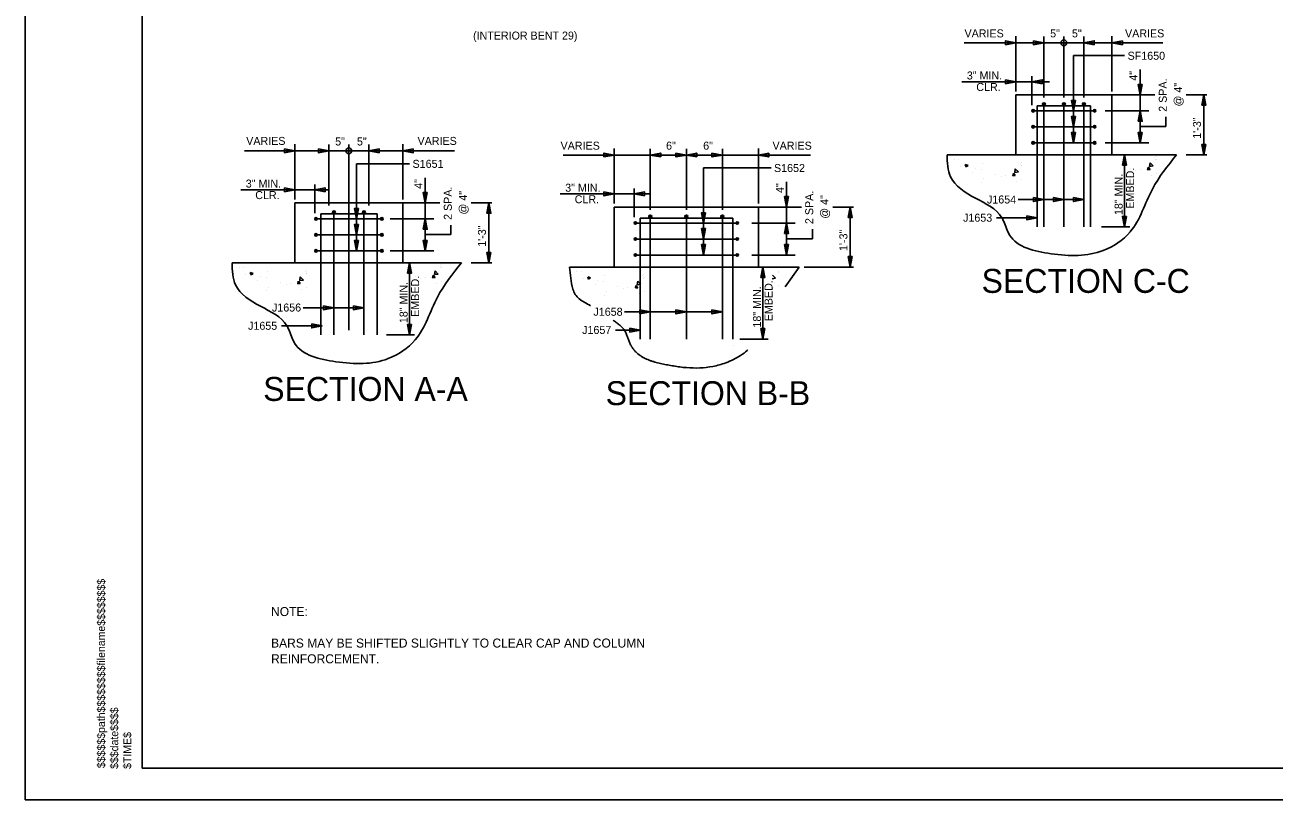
# Model space of a CAD drawing. Extents: x -144.4 to -96.3, y -117.1 to -87.8.
# Drawn here: x -144.35 to -118.31, y -117.06 to -100.91 of the extents above; entities that cross this region are included whole.
import ezdxf

# ---------------------------------------------------------------- set-up
doc = ezdxf.new("R2010")
doc.units = 0
for name, color, linetype in [('BR_AUTO DIMENSION', 7, 'Continuous'), ('BR_BORDER LINES', 7, 'Continuous'), ('BR_CENTER LINES', 7, 'Continuous'), ('BR_CONCRETE', 7, 'Continuous'), ('BR_REBAR', 7, 'Continuous'), ('BR_TEXT', 7, 'Continuous'), ('Level 31', 7, 'Continuous'), ('RD_SHT_ID', 7, 'Continuous')]:
    doc.layers.add(name, color=color, linetype=linetype)

msp = doc.modelspace()

# ---------------------------------------------------------------- linework, layer by layer
at = {"layer": 'BR_AUTO DIMENSION'}
for p, q in [((-123.71, -102.298), (-123.71, -101.149)), ((-123.127, -102.424), (-123.127, -101.154)), ((-122.71, -102.424), (-122.71, -101.154)), ((-122.294, -102.424), (-122.294, -101.154)), ((-121.71, -102.298), (-121.71, -101.149)), ((-124.788, -101.285), (-120.65, -101.285)), ((-121.446, -101.553), (-122.51, -101.553)), ((-122.51, -101.553), (-122.51, -103.369)), ((-123.377, -102.583), (-123.377, -101.984)), ((-121.121, -103.369), (-121.121, -101.845)), ((-124.835, -102.096), (-123.013, -102.096)), ((-121.794, -102.369), (-120.814, -102.369)), ((-120.161, -102.369), (-119.73, -102.369)), ((-119.795, -102.369), (-119.795, -103.619)), ((-121.849, -102.702), (-120.942, -102.702)), ((-120.585, -103.03), (-120.585, -102.831)), ((-121.121, -103.03), (-120.585, -103.03)), ((-139.781, -103.536), (-135.407, -103.536)), ((-138.729, -104.55), (-138.729, -103.401)), ((-138.02, -104.675), (-138.02, -103.406)), ((-137.604, -104.675), (-137.604, -103.406)), ((-137.187, -104.675), (-137.187, -103.406)), ((-136.479, -104.55), (-136.479, -103.401)), ((-133.144, -103.624), (-127.986, -103.624)), ((-132.075, -104.637), (-132.075, -103.488)), ((-131.325, -104.763), (-131.325, -103.494)), ((-130.575, -104.763), (-130.575, -103.494)), ((-129.825, -104.763), (-129.825, -103.494)), ((-129.075, -104.637), (-129.075, -103.488)), ((-121.849, -103.369), (-120.942, -103.369)), ((-121.448, -103.619), (-121.448, -105.119)), ((-120.161, -103.619), (-119.73, -103.619)), ((-136.34, -103.805), (-137.444, -103.805)), ((-137.444, -103.805), (-137.444, -105.62)), ((-136.014, -105.62), (-136.014, -104.097)), ((-128.811, -103.892), (-130.217, -103.892)), ((-130.217, -103.892), (-130.217, -105.708)), ((-139.854, -104.348), (-138.032, -104.348)), ((-138.316, -104.834), (-138.316, -104.235)), ((-131.661, -104.922), (-131.661, -104.323)), ((-128.486, -105.708), (-128.486, -104.185)), ((-136.479, -104.62), (-135.707, -104.62)), ((-135.054, -104.62), (-134.623, -104.62)), ((-134.689, -104.62), (-134.689, -105.87)), ((-133.2, -104.435), (-131.346, -104.435)), ((-122.294, -104.553), (-123.663, -104.553)), ((-129.159, -104.708), (-128.179, -104.708)), ((-127.526, -104.708), (-127.095, -104.708)), ((-127.16, -104.708), (-127.16, -105.958)), ((-136.742, -104.954), (-135.835, -104.954)), ((-135.478, -105.281), (-135.478, -105.083)), ((-129.214, -105.041), (-128.307, -105.041)), ((-127.95, -105.369), (-127.95, -105.171)), ((-123.268, -104.932), (-124.112, -104.932)), ((-121.927, -105.119), (-121.34, -105.119)), ((-136.014, -105.281), (-135.478, -105.281)), ((-128.486, -105.369), (-127.95, -105.369)), ((-136.742, -105.62), (-135.835, -105.62)), ((-129.214, -105.708), (-128.307, -105.708)), ((-136.342, -105.87), (-136.342, -107.37)), ((-135.054, -105.87), (-134.623, -105.87)), ((-128.979, -105.958), (-128.979, -107.458)), ((-128.122, -105.958), (-127.095, -105.958)), ((-137.291, -106.805), (-138.556, -106.805)), ((-129.825, -106.892), (-131.865, -106.892)), ((-138.161, -107.184), (-139.006, -107.184)), ((-131.535, -107.271), (-132.047, -107.271)), ((-136.82, -107.37), (-136.234, -107.37)), ((-129.458, -107.458), (-128.871, -107.458))]:
    msp.add_line(p, q, dxfattribs=at)
for points in [[(-123.926, -101.326), (-123.71, -101.285), (-123.926, -101.243)], [(-123.344, -101.243), (-123.127, -101.285), (-123.344, -101.326)], [(-122.077, -101.326), (-122.294, -101.285), (-122.077, -101.243)], [(-121.493, -101.243), (-121.71, -101.285), (-121.493, -101.326)], [(-123.926, -102.054), (-123.71, -102.096), (-123.926, -102.138)], [(-123.16, -102.138), (-123.377, -102.096), (-123.16, -102.054)], [(-121.079, -102.152), (-121.121, -102.369), (-121.163, -102.152)], [(-122.469, -102.485), (-122.51, -102.702), (-122.552, -102.485)], [(-119.837, -102.585), (-119.795, -102.369), (-119.754, -102.585)], [(-122.469, -102.819), (-122.51, -103.035), (-122.552, -102.819)], [(-121.163, -102.919), (-121.121, -102.702), (-121.079, -102.919)], [(-122.469, -103.152), (-122.51, -103.369), (-122.552, -103.152)], [(-121.079, -103.152), (-121.121, -103.369), (-121.163, -103.152)], [(-138.945, -103.578), (-138.729, -103.536), (-138.945, -103.495)], [(-138.237, -103.495), (-138.02, -103.536), (-138.237, -103.578)], [(-136.97, -103.578), (-137.187, -103.536), (-136.97, -103.495)], [(-136.262, -103.495), (-136.479, -103.536), (-136.262, -103.578)], [(-132.291, -103.665), (-132.075, -103.624), (-132.291, -103.582)], [(-131.108, -103.665), (-131.325, -103.624), (-131.108, -103.582)], [(-130.791, -103.582), (-130.575, -103.624), (-130.791, -103.665)], [(-130.358, -103.665), (-130.575, -103.624), (-130.358, -103.582)], [(-130.041, -103.582), (-129.825, -103.624), (-130.041, -103.665)], [(-128.858, -103.582), (-129.075, -103.624), (-128.858, -103.665)], [(-121.49, -103.835), (-121.448, -103.619), (-121.407, -103.835)], [(-119.754, -103.402), (-119.795, -103.619), (-119.837, -103.402)], [(-138.945, -104.306), (-138.729, -104.348), (-138.945, -104.389)], [(-138.099, -104.389), (-138.316, -104.348), (-138.099, -104.306)], [(-135.973, -104.404), (-136.014, -104.62), (-136.056, -104.404)], [(-132.291, -104.394), (-132.075, -104.435), (-132.291, -104.477)], [(-131.445, -104.477), (-131.661, -104.435), (-131.445, -104.394)], [(-134.73, -104.837), (-134.689, -104.62), (-134.647, -104.837)], [(-128.444, -104.491), (-128.486, -104.708), (-128.527, -104.491)], [(-123.344, -104.511), (-123.127, -104.553), (-123.344, -104.595)], [(-122.927, -104.511), (-122.71, -104.553), (-122.927, -104.595)], [(-122.51, -104.511), (-122.294, -104.553), (-122.51, -104.595)], [(-137.403, -104.737), (-137.444, -104.954), (-137.486, -104.737)], [(-130.176, -104.825), (-130.217, -105.041), (-130.259, -104.825)], [(-127.202, -104.925), (-127.16, -104.708), (-127.119, -104.925)], [(-123.484, -104.891), (-123.268, -104.932), (-123.484, -104.974)], [(-121.407, -104.902), (-121.448, -105.119), (-121.49, -104.902)], [(-137.403, -105.07), (-137.444, -105.287), (-137.486, -105.07)], [(-136.056, -105.17), (-136.014, -104.954), (-135.973, -105.17)], [(-130.176, -105.158), (-130.217, -105.375), (-130.259, -105.158)], [(-128.527, -105.258), (-128.486, -105.041), (-128.444, -105.258)], [(-137.403, -105.404), (-137.444, -105.62), (-137.486, -105.404)], [(-135.973, -105.404), (-136.014, -105.62), (-136.056, -105.404)], [(-134.647, -105.654), (-134.689, -105.87), (-134.73, -105.654)], [(-130.176, -105.491), (-130.217, -105.708), (-130.259, -105.491)], [(-128.444, -105.491), (-128.486, -105.708), (-128.527, -105.491)], [(-136.383, -106.087), (-136.342, -105.87), (-136.3, -106.087)], [(-129.021, -106.175), (-128.979, -105.958), (-128.938, -106.175)], [(-127.119, -105.741), (-127.16, -105.958), (-127.202, -105.741)], [(-138.133, -106.763), (-137.916, -106.805), (-138.133, -106.846)], [(-137.508, -106.763), (-137.291, -106.805), (-137.508, -106.846)], [(-131.541, -106.851), (-131.325, -106.892), (-131.541, -106.934)], [(-130.791, -106.851), (-130.575, -106.892), (-130.791, -106.934)], [(-130.041, -106.851), (-129.825, -106.892), (-130.041, -106.934)], [(-138.378, -107.142), (-138.161, -107.184), (-138.378, -107.226)], [(-136.3, -107.154), (-136.342, -107.37), (-136.383, -107.154)], [(-131.752, -107.23), (-131.535, -107.271), (-131.752, -107.313)], [(-128.938, -107.241), (-128.979, -107.458), (-129.021, -107.241)]]:
    msp.add_lwpolyline(points, close=True, dxfattribs=at)
for centre in [(-122.71, -101.285), (-137.604, -103.536)]:
    msp.add_circle(centre, 0.06, dxfattribs=at)
at = {"layer": 'BR_BORDER LINES'}
for q in [(-141.912, -88.468), (-97.136, -116.398)]:
    msp.add_line((-141.912, -116.398), q, dxfattribs=at)
at = {"layer": 'BR_CENTER LINES'}
msp.add_line((-137.604, -104.353), (-137.604, -107.275), dxfattribs=at)
at = {"layer": 'BR_CONCRETE'}
for p, q in [((-123.71, -102.369), (-121.71, -102.369)), ((-123.71, -102.369), (-123.71, -103.619)), ((-121.71, -102.369), (-121.71, -103.619)), ((-125.143, -103.619), (-120.363, -103.619)), ((-124.99, -103.715), (-124.99, -103.715)), ((-124.899, -103.713), (-124.899, -103.713)), ((-124.858, -103.867), (-124.858, -103.867)), ((-124.766, -103.879), (-124.766, -103.879)), ((-124.707, -103.844), (-124.765, -103.821)), ((-124.748, -103.872), (-124.765, -103.822)), ((-124.707, -103.844), (-124.748, -103.872)), ((-124.413, -103.797), (-124.413, -103.797)), ((-123.62, -103.795), (-123.62, -103.795)), ((-123.6, -103.848), (-123.6, -103.848)), ((-123.598, -103.776), (-123.598, -103.776)), ((-123.592, -103.843), (-123.592, -103.843)), ((-120.966, -103.93), (-120.956, -103.877)), ((-120.916, -103.925), (-120.956, -103.877)), ((-120.925, -103.864), (-120.916, -103.785)), ((-120.851, -103.852), (-120.925, -103.864)), ((-120.851, -103.852), (-120.916, -103.785)), ((-120.813, -103.67), (-120.813, -103.67)), ((-120.793, -103.723), (-120.793, -103.723)), ((-120.791, -103.651), (-120.791, -103.651)), ((-120.785, -103.718), (-120.785, -103.718)), ((-124.613, -103.979), (-124.613, -103.979)), ((-124.558, -103.906), (-124.558, -103.906)), ((-124.43, -103.925), (-124.43, -103.925)), ((-124.383, -104.122), (-124.383, -104.122)), ((-124.136, -104.027), (-124.136, -104.027)), ((-124.018, -104.066), (-124.018, -104.066)), ((-123.927, -104.055), (-123.927, -104.055)), ((-123.773, -104.055), (-123.763, -104.002)), ((-123.723, -104.05), (-123.773, -104.054)), ((-123.723, -104.05), (-123.763, -104.002)), ((-123.732, -103.989), (-123.723, -103.91)), ((-123.658, -103.977), (-123.732, -103.989)), ((-123.658, -103.977), (-123.723, -103.91)), ((-123.59, -104.125), (-123.59, -104.125)), ((-121.333, -104.067), (-121.333, -104.067)), ((-121.328, -103.902), (-121.328, -103.902)), ((-121.242, -104.065), (-121.242, -104.065)), ((-121.211, -103.941), (-121.211, -103.941)), ((-121.12, -103.93), (-121.12, -103.93)), ((-120.916, -103.925), (-120.966, -103.929)), ((-120.888, -104.048), (-120.888, -104.048)), ((-120.783, -104), (-120.783, -104)), ((-124.42, -104.203), (-124.42, -104.203)), ((-123.695, -104.173), (-123.695, -104.173)), ((-138.729, -104.62), (-136.479, -104.62)), ((-138.729, -104.62), (-138.729, -105.87)), ((-136.479, -104.62), (-136.479, -105.87)), ((-132.075, -104.708), (-129.075, -104.708)), ((-132.075, -104.708), (-132.075, -105.958)), ((-129.075, -104.708), (-129.075, -105.958)), ((-140.036, -105.87), (-135.257, -105.87)), ((-139.883, -105.967), (-139.883, -105.967)), ((-139.792, -105.965), (-139.792, -105.965)), ((-135.706, -105.922), (-135.706, -105.922)), ((-135.684, -105.903), (-135.684, -105.903)), ((-135.678, -105.97), (-135.678, -105.97)), ((-133.007, -105.958), (-128.228, -105.958)), ((-128.519, -106.372), (-128.228, -105.958)), ((-139.751, -106.118), (-139.751, -106.118)), ((-139.66, -106.131), (-139.66, -106.131)), ((-139.6, -106.095), (-139.658, -106.073)), ((-139.642, -106.123), (-139.658, -106.073)), ((-139.6, -106.095), (-139.641, -106.123)), ((-139.506, -106.231), (-139.506, -106.231)), ((-139.451, -106.158), (-139.451, -106.158)), ((-139.323, -106.177), (-139.323, -106.177)), ((-139.306, -106.048), (-139.306, -106.048)), ((-138.626, -106.241), (-138.616, -106.162)), ((-138.551, -106.229), (-138.626, -106.241)), ((-138.551, -106.229), (-138.616, -106.161)), ((-138.513, -106.047), (-138.513, -106.047)), ((-138.494, -106.099), (-138.494, -106.099)), ((-138.491, -106.028), (-138.491, -106.028)), ((-138.485, -106.095), (-138.485, -106.095)), ((-136.222, -106.154), (-136.222, -106.154)), ((-136.104, -106.193), (-136.104, -106.193)), ((-136.013, -106.181), (-136.013, -106.181)), ((-135.859, -106.181), (-135.849, -106.129)), ((-135.809, -106.177), (-135.859, -106.181)), ((-135.809, -106.177), (-135.849, -106.129)), ((-135.818, -106.116), (-135.809, -106.037)), ((-135.744, -106.104), (-135.818, -106.116)), ((-135.744, -106.104), (-135.809, -106.036)), ((-135.687, -105.974), (-135.687, -105.974)), ((-132.854, -106.055), (-132.854, -106.055)), ((-132.763, -106.052), (-132.763, -106.052)), ((-132.722, -106.206), (-132.722, -106.206)), ((-132.63, -106.218), (-132.63, -106.218)), ((-132.571, -106.183), (-132.629, -106.161)), ((-132.612, -106.211), (-132.629, -106.161)), ((-132.571, -106.183), (-132.612, -106.211)), ((-132.277, -106.136), (-132.277, -106.136)), ((-131.484, -106.135), (-131.484, -106.135)), ((-131.465, -106.187), (-131.465, -106.187)), ((-131.462, -106.115), (-131.462, -106.115)), ((-131.456, -106.182), (-131.456, -106.182)), ((-128.715, -106.192), (-128.789, -106.203)), ((-128.715, -106.192), (-128.78, -106.124)), ((-128.658, -106.062), (-128.658, -106.062)), ((-128.649, -106.057), (-128.649, -106.057)), ((-139.313, -106.454), (-139.313, -106.454)), ((-139.276, -106.374), (-139.276, -106.374)), ((-139.029, -106.279), (-139.029, -106.279)), ((-138.911, -106.318), (-138.911, -106.318)), ((-138.82, -106.306), (-138.82, -106.306)), ((-138.666, -106.306), (-138.657, -106.254)), ((-138.616, -106.302), (-138.666, -106.306)), ((-138.616, -106.302), (-138.656, -106.254)), ((-138.589, -106.425), (-138.589, -106.425)), ((-138.484, -106.376), (-138.484, -106.376)), ((-136.226, -106.319), (-136.226, -106.319)), ((-136.135, -106.317), (-136.135, -106.317)), ((-135.782, -106.3), (-135.782, -106.3)), ((-135.677, -106.252), (-135.677, -106.252)), ((-132.477, -106.319), (-132.477, -106.319)), ((-132.422, -106.246), (-132.422, -106.246)), ((-132.294, -106.265), (-132.294, -106.265)), ((-132.247, -106.462), (-132.247, -106.462)), ((-132, -106.366), (-132, -106.366)), ((-131.882, -106.405), (-131.882, -106.405)), ((-131.791, -106.394), (-131.791, -106.394)), ((-131.637, -106.394), (-131.627, -106.342)), ((-131.587, -106.389), (-131.637, -106.394)), ((-131.587, -106.389), (-131.627, -106.341)), ((-131.596, -106.328), (-131.587, -106.249)), ((-131.522, -106.317), (-131.596, -106.328)), ((-131.522, -106.317), (-131.587, -106.249)), ((-131.454, -106.464), (-131.454, -106.464)), ((-128.984, -106.269), (-128.984, -106.269)), ((-128.773, -106.404), (-128.773, -106.404)), ((-128.752, -106.388), (-128.752, -106.388)), ((-128.742, -106.28), (-128.742, -106.28)), ((-128.647, -106.339), (-128.647, -106.339)), ((-132.284, -106.542), (-132.284, -106.542)), ((-131.559, -106.513), (-131.559, -106.513))]:
    msp.add_line(p, q, dxfattribs=at)
for points in [[(-125.143, -103.619), (-125.073, -104.077), (-124.552, -104.523), (-124.002, -104.931), (-123.964, -105.007), (-123.841, -105.291), (-122.979, -105.68), (-121.89, -105.613), (-121.331, -105.225), (-120.867, -104.333), (-120.363, -103.619)], [(-140.036, -105.87), (-139.966, -106.329), (-139.445, -106.775), (-138.896, -107.182), (-138.858, -107.258), (-138.735, -107.543), (-137.873, -107.931), (-136.783, -107.865), (-136.224, -107.476), (-135.76, -106.585), (-135.257, -105.87)], [(-133.007, -105.958), (-132.937, -106.417), (-132.891, -106.529), (-132.805, -106.619), (-132.692, -106.695), (-132.569, -106.764)], [(-132.102, -107.067), (-132.038, -107.111), (-131.976, -107.159), (-131.919, -107.211), (-131.892, -107.24), (-131.879, -107.255), (-131.866, -107.27), (-131.845, -107.307), (-131.829, -107.346), (-131.813, -107.381), (-131.799, -107.417), (-131.773, -107.488), (-131.744, -107.56), (-131.726, -107.595), (-131.716, -107.613), (-131.705, -107.63), (-131.669, -107.68), (-131.628, -107.726), (-131.536, -107.802), (-131.485, -107.835), (-131.432, -107.863), (-131.321, -107.909), (-131.261, -107.928), (-131.202, -107.945), (-131.082, -107.974), (-130.961, -107.998), (-130.843, -108.019), (-130.709, -108.04), (-130.573, -108.054), (-130.297, -108.06), (-130.022, -108.028), (-129.887, -107.996), (-129.754, -107.953), (-129.594, -107.884), (-129.444, -107.799), (-129.309, -107.694), (-129.295, -107.68)]]:
    msp.add_spline(points, degree=3, dxfattribs=at)
at = {"layer": 'BR_REBAR'}
for p, q in [((-123.127, -102.535), (-123.127, -105.119)), ((-122.71, -102.535), (-122.71, -105.119)), ((-122.294, -102.535), (-122.294, -105.119)), ((-123.377, -102.702), (-122.044, -102.702)), ((-123.268, -102.598), (-123.268, -105.119)), ((-123.268, -102.598), (-122.153, -102.598)), ((-122.153, -102.598), (-122.153, -105.119)), ((-123.377, -103.035), (-122.044, -103.035)), ((-123.377, -103.369), (-122.044, -103.369)), ((-138.19, -104.85), (-138.19, -107.37)), ((-138.19, -104.85), (-137.018, -104.85)), ((-137.916, -104.787), (-137.916, -107.37)), ((-137.291, -104.787), (-137.291, -107.37)), ((-137.018, -104.85), (-137.018, -107.37)), ((-131.325, -104.875), (-131.325, -107.458)), ((-130.575, -104.875), (-130.575, -107.458)), ((-129.825, -104.875), (-129.825, -107.458)), ((-138.316, -104.954), (-136.892, -104.954)), ((-131.661, -105.041), (-129.488, -105.041)), ((-131.535, -104.937), (-131.535, -107.458)), ((-131.535, -104.937), (-129.608, -104.937)), ((-129.608, -104.937), (-129.608, -107.458)), ((-138.316, -105.287), (-136.892, -105.287)), ((-131.661, -105.375), (-129.488, -105.375)), ((-138.316, -105.62), (-136.892, -105.62)), ((-131.661, -105.708), (-129.488, -105.708))]:
    msp.add_line(p, q, dxfattribs=at)
for centre, radius in [((-123.127, -102.567), 0.0313), ((-122.71, -102.567), 0.0313), ((-122.294, -102.567), 0.0313), ((-123.351, -102.702), 0.026), ((-122.07, -102.702), 0.026), ((-123.351, -103.035), 0.026), ((-122.07, -103.035), 0.026), ((-123.351, -103.369), 0.026), ((-122.07, -103.369), 0.026), ((-138.29, -104.954), 0.026), ((-137.916, -104.818), 0.0313), ((-137.291, -104.818), 0.0313), ((-136.918, -104.954), 0.026), ((-131.325, -104.906), 0.0313), ((-130.575, -104.906), 0.0313), ((-129.825, -104.906), 0.0313), ((-131.635, -105.041), 0.026), ((-129.514, -105.041), 0.026), ((-138.29, -105.287), 0.026), ((-136.918, -105.287), 0.026), ((-131.635, -105.375), 0.026), ((-129.514, -105.375), 0.026), ((-138.29, -105.62), 0.026), ((-136.918, -105.62), 0.026), ((-131.635, -105.708), 0.026), ((-129.514, -105.708), 0.026)]:
    msp.add_circle(centre, radius, dxfattribs=at)
at = {"layer": 'Level 31'}
for points in [[(-144.35, -117.062), (-96.47, -117.062), (-96.47, -87.803), (-144.35, -87.803)], [(-129.599, -107.595), (-129.599, -107.595), (-129.599, -107.595), (-129.599, -107.595)]]:
    msp.add_lwpolyline(points, close=True, dxfattribs=at)

# ---------------------------------------------------------------- texts
at = {"layer": 'BR_AUTO DIMENSION'}
for s, rotation, p in [('VARIES', 360, (-124.781, -101.173)), ('5"', 360, (-122.997, -101.173)), ('5"', 360, (-122.542, -101.173)), ('VARIES', 360, (-121.437, -101.173)), ('3" MIN.', 360, (-124.733, -102.05)), ('4"', 90, (-121.179, -102.076)), ('2 SPA.', 90, (-120.567, -102.723)), ('CLR.', 360, (-124.535, -102.29)), ('@ 4"', 90, (-120.25, -102.612)), ('1\'-3"', 90, (-119.855, -103.285)), ('VARIES', 360, (-139.743, -103.413)), ('5"', 360, (-137.89, -103.425)), ('5"', 360, (-137.436, -103.425)), ('VARIES', 360, (-136.174, -103.413)), ('VARIES', 360, (-133.195, -103.512)), ('6"', 360, (-130.997, -103.512)), ('6"', 360, (-130.224, -103.512)), ('VARIES', 360, (-128.78, -103.512)), ('3" MIN.', 360, (-139.752, -104.302)), ('4"', 90, (-136.073, -104.328)), ('18" MIN.', 90, (-121.488, -104.875)), ('EMBED.', 90, (-121.248, -104.742)), ('CLR.', 360, (-139.554, -104.542)), ('2 SPA.', 90, (-135.46, -104.975)), ('@ 4"', 90, (-135.143, -104.864)), ('3" MIN.', 360, (-133.098, -104.389)), ('4"', 90, (-128.544, -104.415)), ('2 SPA.', 90, (-127.932, -105.062)), ('CLR.', 360, (-132.9, -104.629)), ('@ 4"', 90, (-127.615, -104.951)), ('1\'-3"', 90, (-134.749, -105.536)), ('1\'-3"', 90, (-127.22, -105.624)), ('EMBED.', 90, (-136.141, -106.995)), ('18" MIN.', 90, (-136.381, -107.127)), ('18" MIN.', 90, (-129.019, -107.219)), ('EMBED.', 90, (-128.779, -107.087))]:
    msp.add_text(s, height=0.1667, rotation=rotation, dxfattribs=at).set_placement(p)
for s, height, p in [('(INTERIOR BENT 29)', 0.16625, (-135.017, -101.218)), ('SF1650', 0.1667, (-121.384, -101.639)), ('S1651', 0.1667, (-136.278, -103.891)), ('S1652', 0.1667, (-128.749, -103.978)), ('J1654', 0.1667, (-124.313, -104.634)), ('J1653', 0.1667, (-124.811, -105.013)), ('J1656', 0.1667, (-139.206, -106.885)), ('J1658', 0.1667, (-132.51, -106.973)), ('J1655', 0.1667, (-139.704, -107.265)), ('J1657', 0.1667, (-132.745, -107.352)), ('NOTE:', 0.1875, (-139.225, -113.23)), ('BARS MAY BE SHIFTED SLIGHTLY TO CLEAR CAP AND COLUMN', 0.1875, (-139.225, -113.886)), ('REINFORCEMENT.', 0.1875, (-139.225, -114.214))]:
    msp.add_text(s, height=height, dxfattribs=at).set_placement(p)
at = {"layer": 'BR_TEXT'}
for s, p in [('SECTION C-C', (-124.424, -106.496)), ('SECTION A-A', (-139.388, -108.747)), ('SECTION B-B', (-132.256, -108.835))]:
    msp.add_text(s, height=0.49875, dxfattribs=at).set_placement(p)
at = {"layer": 'RD_SHT_ID'}
for s, height, p in [('$$$$$$path$$$$$$$$filename$$$$$$$$', 0.16421, (-142.683, -116.398)), ('$$$date$$$$', 0.16421, (-142.409, -116.415)), ('$TIME$', 0.1642, (-142.137, -116.415))]:
    msp.add_text(s, height=height, rotation=90, dxfattribs=at).set_placement(p)

doc.saveas('drawing.dxf')
